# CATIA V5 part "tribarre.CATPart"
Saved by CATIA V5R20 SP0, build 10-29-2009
Part number: tribarre
Bounding box of the stored display mesh (mm): x 2810.778 to 2850.778, y -642.675 to 1246.273, z -653.589 to 1081.183
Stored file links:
  C:\Users\Mike-7\Desktop\MMS_GR3\bfoltzer\CFAO_bfoltzer\tribarre.CATPart
  D:\ecole\thinkmotion\Eolienne.CATProduct
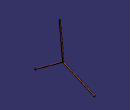
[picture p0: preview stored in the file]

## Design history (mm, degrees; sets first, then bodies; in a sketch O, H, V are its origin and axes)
Set1
  Plane1: linked copy from another document
  Point1: linked copy from another document
  Point2: linked copy from another document
  Plane2: linked copy from another document
  Plane3: linked copy from another document
  Point3: linked copy from another document
  Point4: linked copy from another document
  Plane4: linked copy from another document
  Plane5: linked copy from another document
  Point5: linked copy from another document
  Plane6: linked copy from another document
Body1 (main body)
  Sketch1 on Plane1, origin (0, 1658.1138, 1238.6777), H (-1, 0, 0), V (0, -0.9946, -0.1041)
    circle A1 centre (-2830.7782, 1532.3314) radius 20
    point P1 (-2830.7782, 1532.3314)
    reference projected point E1 (-2830.7782, 1532.3314) from Point1
    reference projected point E2 (-2830.7782, 1512.3314) from Point2
    coincidence: P1 E1, A1 E2
  Pad1: profile Sketch1, direction (0, -0.1041, 0.9946), up to Plane2
  Sketch2 on Plane3, origin (0, 462.6584, -2181.6071), H (-1, 0, 0), V (0, 0.4071, 0.9134)
    circle A1 centre (-2830.7782, 1904.9008) radius 20
    point P1 (-2830.7782, 1904.9008)
    reference projected point E1 (-2830.7782, 1904.9008) from Point3
    reference projected point E2 (-2830.7782, 1924.9008) from Point4
    coincidence: P1 E1, A1 E2
  Pad2: profile Sketch2, direction (0, 0.9134, -0.4071), up to Plane4
  Sketch3 on Plane5, origin (0, -1747.7352, 901.0144), H (1, 0, 0), V (0, -0.5875, 0.8092)
    circle A1 centre (2830.7782, -1901.0508) radius 20
    point P1 (2830.7782, -1901.0508)
    reference projected point E1 (2830.7782, -1901.0508) from Point1
    reference projected point E2 (2830.7782, -1921.0508) from Point5
    coincidence: P1 E1, A1 E2
  Pad3: profile Sketch3, direction (0, -0.8092, -0.5875), up to Plane6
  Fillet1: radius 5, on edge [face of Pad1 from Sketch1.A1 | face of Pad2 from Sketch2.A1]
  Fillet2: radius 5, on edge [face of Pad2 from Sketch2.A1 | face of Pad3 from Sketch3.A1]
  Fillet3: radius 5, on edge [face of Pad1 from Sketch1.A1 | face of Pad3 from Sketch3.A1]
